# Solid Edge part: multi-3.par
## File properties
Author: Deepak Maini
Template: normal.par
Last saved by: MYPC
Revision: 5
Application: Solid Edge
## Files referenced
..\multi-cutout.asm
ED:\sld-edg-15\cd-models\c09-sld-edg-15\figure28-8&29\multi-cutout.asm
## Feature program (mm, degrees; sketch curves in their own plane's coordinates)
sketch for "unnamed Protrusion 1" plane through (0, 0, 0) normal (0, 0, 1) x-axis (1, 0, 0)
  circle centre (0, 0) radius 37.9639
extrude "unnamed Protrusion 1" add finite 26.55 along +normal
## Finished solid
Body 1: solid body, 3 faces, 2 edges, 0 vertices.
  Faces by surface: plane 2, cylinder 1
  Edges by curve: circle 2
Bounding box of the edges (mm): 75.928 x 75.928 x 26.550, from (-37.9639, -37.9639, 0) to (37.9639, 37.9639, 26.55).
Cylindrical faces by radius (mm): R37.9639 x1
Planar faces by outward normal: +z 1, -z 1
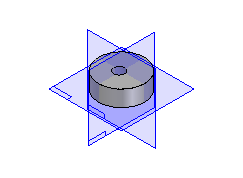
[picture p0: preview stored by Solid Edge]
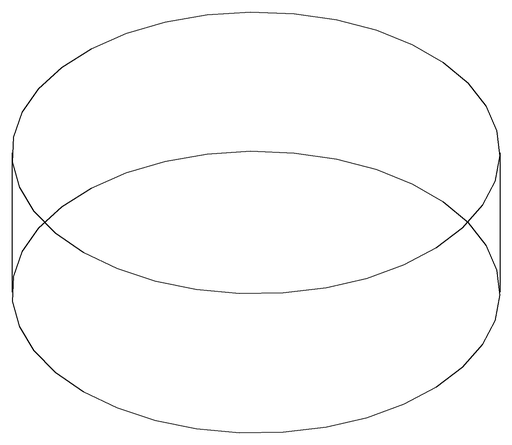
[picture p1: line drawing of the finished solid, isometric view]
